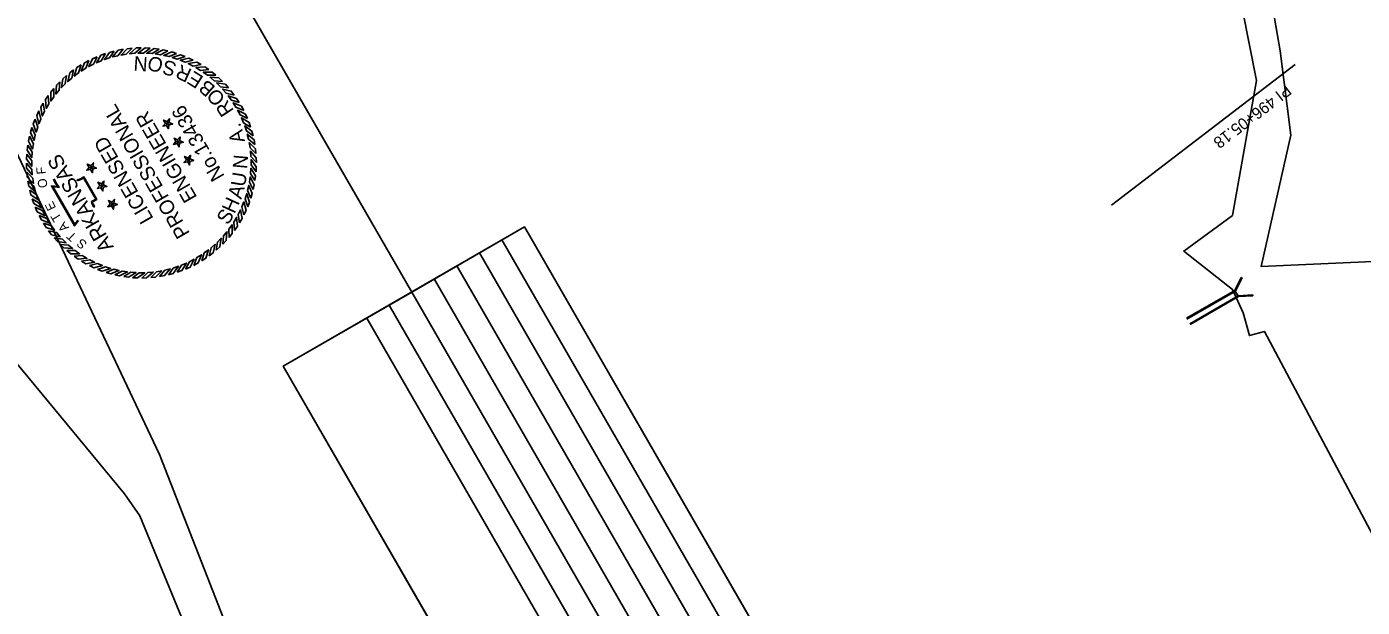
# Model space of a CAD drawing. Extents: x 956270 to 957915, y 1920520 to 1922423.
# Drawn here: x 956617 to 957310, y 1921739 to 1922039 of the extents above; entities that cross this region are included whole.
import ezdxf

# ---------------------------------------------------------------- set-up
doc = ezdxf.new("R2010")
doc.units = 0
for name, color, linetype in [('1', 7, 'Continuous'), ('Default', 7, 'Continuous'), ('G-ANNO-SYMB', 7, 'Continuous'), ('NO PLOT', 7, 'Continuous'), ('R_Drainage', 7, 'Continuous'), ('R_Horz Alg Annot', 7, 'Continuous')]:
    doc.layers.add(name, color=color, linetype=linetype)

msp = doc.modelspace()

# ---------------------------------------------------------------- linework, layer by layer
at = {"layer": '1'}
msp.add_line((956816.66, 1921901.98), (956666.17, 1922162.65), dxfattribs=at)
at = {"layer": 'Default'}
for p, q in [((956749.98, 1921863.48), (956875.12, 1921935.73)), ((957087.62, 1921567.67), (956875.12, 1921935.73)), ((957075.93, 1921560.92), (956863.43, 1921928.98)), ((957064.24, 1921554.17), (956851.74, 1921922.23)), ((957052.55, 1921547.42), (956840.05, 1921915.48)), ((957040.85, 1921540.67), (956828.35, 1921908.73)), ((957040.85, 1921540.67), (956828.35, 1921908.73)), ((957029.16, 1921533.92), (956816.66, 1921901.98)), ((957017.47, 1921527.17), (956804.97, 1921895.23)), ((957005.78, 1921520.42), (956793.28, 1921888.48)), ((956962.48, 1921495.42), (956749.98, 1921863.48))]:
    msp.add_line(p, q, dxfattribs=at)
at = {"layer": 'G-ANNO-SYMB'}
for points in [[(956657.79, 1922025.59), (956655.37, 1922024.73), (956653.02, 1922020.81), (956655.57, 1922021.89)], [(956662.3, 1922026.87), (956659.82, 1922026.21), (956657.17, 1922022.49), (956659.8, 1922023.36)], [(956666.89, 1922027.79), (956664.37, 1922027.33), (956661.43, 1922023.83), (956664.12, 1922024.49)], [(956671.54, 1922028.35), (956668.99, 1922028.09), (956665.79, 1922024.83), (956668.52, 1922025.28)], [(956676.22, 1922028.55), (956673.66, 1922028.49), (956670.21, 1922025.49), (956672.97, 1922025.72)], [(956680.9, 1922028.38), (956678.34, 1922028.52), (956674.67, 1922025.8), (956677.44, 1922025.81)], [(956685.56, 1922027.84), (956683.02, 1922028.18), (956679.14, 1922025.76), (956681.9, 1922025.55)], [(956690.15, 1922026.93), (956687.65, 1922027.47), (956683.59, 1922025.36), (956686.33, 1922024.94)], [(956694.67, 1922025.67), (956692.21, 1922026.41), (956688, 1922024.62), (956690.7, 1922023.99)], [(956645.07, 1922019.68), (956642.92, 1922018.29), (956641.54, 1922013.93), (956643.78, 1922015.57)], [(956649.15, 1922021.98), (956646.9, 1922020.76), (956645.18, 1922016.52), (956647.54, 1922017.98)], [(956653.4, 1922023.95), (956651.06, 1922022.92), (956649.02, 1922018.82), (956651.48, 1922020.1)], [(956699.07, 1922024.06), (956696.67, 1922024.99), (956692.34, 1922023.54), (956694.98, 1922022.7)], [(956703.32, 1922022.11), (956701.01, 1922023.22), (956696.57, 1922022.12), (956699.14, 1922021.07)], [(956707.42, 1922019.83), (956705.2, 1922021.12), (956700.69, 1922020.37), (956703.16, 1922019.12)], [(956711.32, 1922017.24), (956709.21, 1922018.7), (956704.65, 1922018.3), (956707.02, 1922016.86)], [(956637.51, 1922014.16), (956635.6, 1922012.45), (956634.93, 1922007.93), (956636.88, 1922009.9)], [(956641.18, 1922017.07), (956639.15, 1922015.51), (956638.12, 1922011.06), (956640.21, 1922012.87)], [(956715, 1922014.35), (956713.01, 1922015.97), (956708.44, 1922015.93), (956710.69, 1922014.31)], [(956718.45, 1922011.18), (956716.59, 1922012.95), (956712.03, 1922013.27), (956714.15, 1922011.48)], [(956630.91, 1922007.53), (956629.29, 1922005.54), (956629.33, 1922000.96), (956630.95, 1922003.22)], [(956634.08, 1922010.97), (956632.31, 1922009.12), (956631.99, 1922004.56), (956633.78, 1922006.67)], [(956721.64, 1922007.75), (956719.93, 1922009.66), (956715.4, 1922010.33), (956717.37, 1922008.38)], [(956724.55, 1922004.07), (956722.99, 1922006.11), (956718.54, 1922007.14), (956720.35, 1922005.04)], [(956625.42, 1921999.94), (956624.14, 1921997.72), (956624.89, 1921993.21), (956626.14, 1921995.69)], [(956628.02, 1922003.84), (956626.56, 1922001.73), (956626.96, 1921997.17), (956628.39, 1921999.55)], [(956727.16, 1922000.18), (956725.77, 1922002.34), (956721.41, 1922003.71), (956723.05, 1922001.48)], [(956729.46, 1921996.1), (956728.24, 1921998.36), (956724, 1922000.07), (956725.46, 1921997.72)], [(956621.19, 1921991.59), (956620.27, 1921989.2), (956621.72, 1921984.86), (956622.56, 1921987.5)], [(956623.15, 1921995.85), (956622.04, 1921993.53), (956623.14, 1921989.1), (956624.19, 1921991.66)], [(956689.9, 1921989.3), (956689.68, 1921990.32), (956687.87, 1921991.13), (956688.86, 1921989.41)], [(956689.9, 1921989.3), (956690.8, 1921989.82), (956691.01, 1921991.79), (956689.68, 1921990.32)], [(956731.43, 1921991.85), (956730.39, 1921994.2), (956726.3, 1921996.24), (956727.57, 1921993.78)], [(956733.06, 1921987.46), (956732.21, 1921989.88), (956728.29, 1921992.24), (956729.37, 1921989.68)], [(956619.58, 1921987.19), (956618.85, 1921984.73), (956620.64, 1921980.52), (956621.27, 1921983.22)], [(956689.9, 1921989.3), (956688.86, 1921989.41), (956687.54, 1921987.94), (956689.48, 1921988.35)], [(956689.9, 1921989.3), (956689.48, 1921988.35), (956690.47, 1921986.63), (956690.67, 1921988.6)], [(956689.9, 1921989.3), (956690.67, 1921988.6), (956692.61, 1921989.02), (956690.8, 1921989.82)], [(956734.34, 1921982.96), (956733.69, 1921985.44), (956729.96, 1921988.09), (956730.83, 1921985.46)], [(956735.27, 1921978.36), (956734.81, 1921980.89), (956731.3, 1921983.83), (956731.97, 1921981.14)], [(956617.42, 1921978.08), (956617.08, 1921975.54), (956619.5, 1921971.66), (956619.7, 1921974.43)], [(956618.32, 1921982.68), (956617.78, 1921980.17), (956619.89, 1921976.11), (956620.31, 1921978.85)], [(956695.36, 1921979.85), (956694.32, 1921979.96), (956692.99, 1921978.49), (956694.93, 1921978.9)], [(956695.36, 1921979.85), (956695.14, 1921980.87), (956693.33, 1921981.68), (956694.32, 1921979.96)], [(956695.36, 1921979.85), (956694.93, 1921978.9), (956695.92, 1921977.19), (956696.13, 1921979.16)], [(956695.36, 1921979.85), (956696.26, 1921980.37), (956696.46, 1921982.34), (956695.14, 1921980.87)], [(956695.36, 1921979.85), (956696.13, 1921979.16), (956698.07, 1921979.57), (956696.26, 1921980.37)], [(956735.83, 1921973.71), (956735.57, 1921976.27), (956732.31, 1921979.47), (956732.76, 1921976.74)], [(956616.88, 1921973.43), (956616.74, 1921970.87), (956619.46, 1921967.19), (956619.44, 1921969.96)], [(956700.81, 1921970.41), (956699.77, 1921970.51), (956698.45, 1921969.04), (956700.39, 1921969.45)], [(956700.81, 1921970.41), (956700.59, 1921971.42), (956698.78, 1921972.23), (956699.77, 1921970.51)], [(956700.81, 1921970.41), (956700.39, 1921969.45), (956701.38, 1921967.74), (956701.58, 1921969.71)], [(956700.81, 1921970.41), (956701.71, 1921970.93), (956701.92, 1921972.9), (956700.59, 1921971.42)], [(956700.81, 1921970.41), (956701.58, 1921969.71), (956703.52, 1921970.12), (956701.71, 1921970.93)], [(956736.03, 1921969.03), (956735.96, 1921971.6), (956732.96, 1921975.05), (956733.2, 1921972.29)], [(956735.85, 1921964.35), (956735.99, 1921966.91), (956733.27, 1921970.59), (956733.29, 1921967.82)], [(956616.71, 1921968.75), (956616.77, 1921966.18), (956619.77, 1921962.73), (956619.54, 1921965.49)], [(956616.9, 1921964.07), (956617.17, 1921961.51), (956620.43, 1921958.31), (956619.98, 1921961.04)], [(956650.34, 1921966.46), (956649.3, 1921966.57), (956647.98, 1921965.1), (956649.91, 1921965.51)], [(956650.34, 1921966.46), (956650.12, 1921967.48), (956648.31, 1921968.28), (956649.3, 1921966.57)], [(956650.34, 1921966.46), (956649.91, 1921965.51), (956650.91, 1921963.79), (956651.11, 1921965.76)], [(956650.34, 1921966.46), (956651.24, 1921966.98), (956651.45, 1921968.95), (956650.12, 1921967.48)], [(956650.34, 1921966.46), (956651.11, 1921965.76), (956653.05, 1921966.17), (956651.24, 1921966.98)], [(956735.31, 1921959.7), (956735.65, 1921962.24), (956733.23, 1921966.12), (956733.03, 1921963.36)], [(956617.46, 1921959.42), (956617.93, 1921956.89), (956621.43, 1921953.95), (956620.77, 1921956.64)], [(956655.79, 1921957.01), (956654.76, 1921957.12), (956653.43, 1921955.65), (956655.37, 1921956.06)], [(956655.79, 1921957.01), (956655.58, 1921958.03), (956653.77, 1921958.84), (956654.76, 1921957.12)], [(956655.79, 1921957.01), (956655.37, 1921956.06), (956656.36, 1921954.34), (956656.57, 1921956.32)], [(956655.79, 1921957.01), (956656.7, 1921957.53), (956656.9, 1921959.5), (956655.58, 1921958.03)], [(956655.79, 1921957.01), (956656.57, 1921956.32), (956658.51, 1921956.73), (956656.7, 1921957.53)], [(956733.15, 1921950.59), (956733.88, 1921953.05), (956732.1, 1921957.26), (956731.47, 1921954.56)], [(956734.41, 1921955.1), (956734.95, 1921957.61), (956732.84, 1921961.67), (956732.42, 1921958.93)], [(956618.39, 1921954.82), (956619.05, 1921952.34), (956622.77, 1921949.69), (956621.9, 1921952.32)], [(956619.67, 1921950.32), (956620.52, 1921947.9), (956624.44, 1921945.54), (956623.37, 1921948.1)], [(956661.25, 1921947.56), (956661.03, 1921948.58), (956659.22, 1921949.39), (956660.21, 1921947.67)], [(956661.25, 1921947.56), (956662.15, 1921948.09), (956662.36, 1921950.06), (956661.03, 1921948.58)], [(956731.54, 1921946.19), (956732.46, 1921948.59), (956731.01, 1921952.92), (956730.17, 1921950.28)], [(956621.3, 1921945.93), (956622.34, 1921943.58), (956626.43, 1921941.54), (956625.16, 1921944)], [(956661.25, 1921947.56), (956660.21, 1921947.67), (956658.89, 1921946.2), (956660.82, 1921946.61)], [(956661.25, 1921947.56), (956660.82, 1921946.61), (956661.81, 1921944.9), (956662.02, 1921946.87)], [(956661.25, 1921947.56), (956662.02, 1921946.87), (956663.96, 1921947.28), (956662.15, 1921948.09)], [(956727.31, 1921937.84), (956728.6, 1921940.06), (956727.84, 1921944.57), (956726.6, 1921942.09)], [(956729.59, 1921941.93), (956730.7, 1921944.25), (956729.59, 1921948.68), (956728.55, 1921946.12)], [(956623.28, 1921941.68), (956624.49, 1921939.42), (956628.73, 1921937.71), (956627.27, 1921940.06)], [(956625.57, 1921937.6), (956626.97, 1921935.44), (956631.33, 1921934.07), (956629.69, 1921936.3)], [(956721.83, 1921930.25), (956723.44, 1921932.24), (956723.4, 1921936.82), (956721.79, 1921934.57)], [(956724.72, 1921933.94), (956726.17, 1921936.05), (956725.78, 1921940.61), (956724.34, 1921938.23)], [(956628.19, 1921933.71), (956629.74, 1921931.67), (956634.2, 1921930.64), (956632.39, 1921932.74)], [(956631.09, 1921930.04), (956632.81, 1921928.13), (956637.33, 1921927.45), (956635.36, 1921929.4)], [(956715.22, 1921923.62), (956717.13, 1921925.33), (956717.81, 1921929.85), (956715.86, 1921927.88)], [(956718.65, 1921926.81), (956720.42, 1921928.66), (956720.74, 1921933.22), (956718.95, 1921931.11)], [(956634.28, 1921926.6), (956636.14, 1921924.83), (956640.7, 1921924.51), (956638.58, 1921926.3)], [(956637.73, 1921923.43), (956639.72, 1921921.81), (956644.29, 1921921.85), (956642.04, 1921923.47)], [(956707.66, 1921918.1), (956709.82, 1921919.49), (956711.19, 1921923.85), (956708.96, 1921922.21)], [(956711.55, 1921920.71), (956713.59, 1921922.27), (956714.62, 1921926.72), (956712.52, 1921924.91)], [(956641.42, 1921920.54), (956643.53, 1921919.08), (956648.08, 1921919.48), (956645.71, 1921920.92)], [(956645.32, 1921917.95), (956647.54, 1921916.66), (956652.05, 1921917.41), (956649.57, 1921918.66)], [(956649.41, 1921915.67), (956651.72, 1921914.56), (956656.16, 1921915.66), (956653.59, 1921916.71)], [(956653.67, 1921913.72), (956656.06, 1921912.79), (956660.4, 1921914.24), (956657.76, 1921915.09)], [(956690.43, 1921910.91), (956692.91, 1921911.57), (956695.57, 1921915.29), (956692.94, 1921914.42)], [(956694.94, 1921912.2), (956697.36, 1921913.05), (956699.71, 1921916.97), (956697.16, 1921915.89)], [(956699.33, 1921913.83), (956701.68, 1921914.87), (956703.72, 1921918.96), (956701.25, 1921917.69)], [(956703.58, 1921915.8), (956705.84, 1921917.02), (956707.55, 1921921.26), (956705.19, 1921919.8)], [(956658.07, 1921912.11), (956660.53, 1921911.37), (956664.74, 1921913.16), (956662.04, 1921913.79)], [(956662.58, 1921910.85), (956665.09, 1921910.31), (956669.14, 1921912.42), (956666.4, 1921912.84)], [(956667.18, 1921909.94), (956669.72, 1921909.6), (956673.6, 1921912.03), (956670.83, 1921912.23)], [(956671.83, 1921909.4), (956674.39, 1921909.26), (956678.07, 1921911.98), (956675.29, 1921911.97)], [(956676.51, 1921909.23), (956679.08, 1921909.29), (956682.53, 1921912.29), (956679.76, 1921912.06)], [(956681.19, 1921909.43), (956683.74, 1921909.69), (956686.95, 1921912.95), (956684.21, 1921912.5)], [(956685.84, 1921909.99), (956688.37, 1921910.45), (956691.3, 1921913.95), (956688.61, 1921913.29)]]:
    msp.add_lwpolyline(points, close=True, dxfattribs=at)
for points in [[(956643.65, 1921938.96), (956641.73, 1921936.25), (956629.69, 1921957.09), (956632.88, 1921956.61), (956632.05, 1921958.01), (956631.35, 1921959.19), (956630.8, 1921960.44)], [(956643.34, 1921939.18), (956641.77, 1921936.96), (956630.42, 1921956.59), (956633.62, 1921956.11), (956632.37, 1921958.21), (956631.69, 1921959.36), (956631.14, 1921960.6)], [(956642.8, 1921960), (956643.41, 1921959.77), (956644.06, 1921959.94), (956645.26, 1921960.47), (956646.38, 1921961.12), (956652.72, 1921950.14), (956651.1, 1921949.21), (956650.43, 1921948.82), (956650.63, 1921947.94), (956651.51, 1921946.41), (956651.33, 1921946.04)], [(956642.94, 1921960.36), (956643.43, 1921960.17), (956643.93, 1921960.3), (956645.08, 1921960.81), (956646.52, 1921961.64), (956653.24, 1921950), (956651.3, 1921948.88), (956650.86, 1921948.63), (956650.99, 1921948.08), (956651.95, 1921946.42), (956651.67, 1921945.87)]]:
    msp.add_lwpolyline(points, dxfattribs=at)
at = {"layer": 'NO PLOT'}
for points in [[(957915.18, 1921041.6), (957117.5, 1922423.23), (956666.17, 1922162.65), (956816.66, 1921901.98), (956875.12, 1921935.73), (957087.62, 1921567.67), (957029.16, 1921533.92), (957172.25, 1921286.08), (957225.74, 1921316.96), (957397.07, 1921020.21), (957343.58, 1920989.33), (957463.85, 1920781.02)], [(957915.18, 1921041.6), (957117.5, 1922423.23), (956666.17, 1922162.65), (956816.66, 1921901.98), (956875.12, 1921935.73), (957087.62, 1921567.67), (957029.16, 1921533.92), (957172.25, 1921286.08), (957225.74, 1921316.96), (957397.07, 1921020.21), (957343.58, 1920989.33), (957463.85, 1920781.02)], [(957915.18, 1921041.6), (957117.5, 1922423.23), (956666.17, 1922162.65), (956816.66, 1921901.98), (956875.12, 1921935.73), (957087.62, 1921567.67), (957029.16, 1921533.92), (957172.25, 1921286.08), (957225.74, 1921316.96), (957397.07, 1921020.21), (957343.58, 1920989.33), (957463.85, 1920781.02)], [(957915.18, 1921041.6), (957117.5, 1922423.23), (956666.17, 1922162.65), (956816.66, 1921901.98), (956875.12, 1921935.73), (957087.62, 1921567.67), (957029.16, 1921533.92), (957172.25, 1921286.08), (957225.74, 1921316.96), (957397.07, 1921020.21), (957343.58, 1920989.33), (957463.85, 1920781.02)], [(957012.51, 1920520.44), (956420.48, 1921545.87), (956463.26, 1921570.57), (956365.36, 1921740.14), (956378, 1921747.44), (956270.25, 1921934.07), (956666.17, 1922162.65), (956816.66, 1921901.98), (956749.98, 1921863.48), (956962.48, 1921495.42), (957029.16, 1921533.92), (957172.25, 1921286.08), (957120.9, 1921256.43), (957292.23, 1920959.68), (957343.58, 1920989.33), (957463.85, 1920781.02)], [(957012.51, 1920520.44), (956420.48, 1921545.87), (956463.26, 1921570.57), (956365.36, 1921740.14), (956378, 1921747.44), (956270.25, 1921934.07), (956666.17, 1922162.65), (956816.66, 1921901.98), (956749.98, 1921863.48), (956962.48, 1921495.42), (957029.16, 1921533.92), (957172.25, 1921286.08), (957120.9, 1921256.43), (957292.23, 1920959.68), (957343.58, 1920989.33), (957463.85, 1920781.02)], [(957012.51, 1920520.44), (956420.48, 1921545.87), (956463.26, 1921570.57), (956365.36, 1921740.14), (956378, 1921747.44), (956270.25, 1921934.07), (956666.17, 1922162.65), (956816.66, 1921901.98), (956749.98, 1921863.48), (956962.48, 1921495.42), (957029.16, 1921533.92), (957172.25, 1921286.08), (957120.9, 1921256.43), (957292.23, 1920959.68), (957343.58, 1920989.33), (957463.85, 1920781.02)], [(957012.51, 1920520.44), (956420.48, 1921545.87), (956463.26, 1921570.57), (956365.36, 1921740.14), (956378, 1921747.44), (956270.25, 1921934.07), (956666.17, 1922162.65), (956816.66, 1921901.98), (956749.98, 1921863.48), (956962.48, 1921495.42), (957029.16, 1921533.92), (957172.25, 1921286.08), (957120.9, 1921256.43), (957292.23, 1920959.68), (957343.58, 1920989.33), (957463.85, 1920781.02)]]:
    msp.add_lwpolyline(points, close=True, dxfattribs=at)
for points in [[(957342.58, 1921919.03), (957257.4, 1921915.24), (957272.85, 1921983.36), (957267.37, 1922027.06), (957246.99, 1922143.57)], [(957240.29, 1922085.93), (957255.08, 1922011.58), (957242.6, 1921941.72), (957217.28, 1921923.16), (957242.63, 1921903.32), (957248.1, 1921891.14), (957251.36, 1921879.39), (957259.14, 1921881.52), (957406.57, 1921604.71)], [(956978.43, 1921300.96), (956891.96, 1921416.34), (956761.21, 1921624.84), (956685.68, 1921817.75), (956598.64, 1922001.42), (956569.16, 1922006.84), (956549.42, 1922003.64), (956496.56, 1922078), (956484.6, 1922065.05), (956487.74, 1922034.93), (956520.15, 1921988.76), (956538.43, 1921986.13), (956552.84, 1921975.42), (956577.89, 1921905.71), (956667.63, 1921797.4), (956675.52, 1921785.98), (956734.33, 1921642.98), (956883.87, 1921386.21), (956963.43, 1921282.81)]]:
    msp.add_lwpolyline(points, dxfattribs=at)
at = {"layer": 'R_Drainage'}
for p, q in [((957247.09, 1921909.51), (957243.74, 1921902.8)), ((957247.54, 1921909.28), (957244.12, 1921902.44)), ((957247.09, 1921909.51), (957247.54, 1921909.28)), ((957218.72, 1921888.41), (957243.74, 1921902.8)), ((957218.96, 1921887.98), (957244.12, 1921902.44)), ((957242.87, 1921902.3), (957244.85, 1921899.1)), ((957243.74, 1921902.8), (957245.71, 1921899.6)), ((957220.4, 1921885.55), (957245.57, 1921900.08)), ((957220.65, 1921885.12), (957245.72, 1921899.59)), ((957253.18, 1921900.53), (957245.57, 1921900.08)), ((957253.2, 1921900.03), (957245.72, 1921899.59)), ((957253.2, 1921900.03), (957253.18, 1921900.53))]:
    msp.add_line(p, q, dxfattribs=at)
at = {"layer": 'R_Horz Alg Annot'}
msp.add_lwpolyline([(957179.79, 1921946.96), (957275.07, 1922019.91)], dxfattribs=at)

# ---------------------------------------------------------------- texts
at = {"layer": 'G-ANNO-SYMB'}
for s, height, rotation, p in [('N', 7.5, 176.10067, (956679.85, 1922023.72)), ('O', 7.5, 164.77573, (956688.31, 1922022.59)), ('S', 7.5, 163.48784, (956695.19, 1922020.61)), ('R', 7.5, 155.65967, (956703.05, 1922017.19)), ('E', 7.5, 147.83149, (956709.1, 1922013.36)), ('B', 7.5, 138.88501, (956715.23, 1922008.15)), ('O', 7.5, 131.42961, (956720.37, 1922002.44)), ('PROFESSIONAL', 7.5, 120, (956701.76, 1921932.41)), ('No.13436', 7.47, 120, (956719.78, 1921962.05)), ('R', 7.5, 123.22866, (956724.63, 1921996.03)), ('ENGINEER', 7.5, 120, (956705.48, 1921951.06)), ('A', 7.5, 103.09908, (956730.2, 1921980.12)), ('.', 7.5, 111.30002, (956728.4, 1921987.59)), ('LICENSED', 7.5, 120, (956682.86, 1921940.06)), ('ARKANSAS', 7.747, 120, (956662.16, 1921925.33)), ('N', 7.5, 84.93262, (956731.16, 1921965.58)), ('F', 4.75, 95.36282, (956626.82, 1921963.19)), ('U', 7.5, 80.90262, (956730.1, 1921956.24)), ('O', 4.75, 101.2218, (956627.85, 1921956.4)), ('A', 7.5, 73.44722, (956728.21, 1921949.75)), ('H', 7.5, 65.61905, (956724.66, 1921942.2)), ('E', 4.75, 116.67203, (956632.2, 1921945.6)), ('S', 7.5, 58.16364, (956721.28, 1921936.3)), ('T', 4.75, 121.47887, (956635.11, 1921940.27)), ('A', 4.75, 128.67877, (956639, 1921935.43)), ('T', 4.75, 136.90148, (956643.18, 1921931.19)), ('S', 4.75, 139.77256, (956648.55, 1921927.32))]:
    msp.add_text(s, height=height, rotation=rotation, dxfattribs=at).set_placement(p)
at = {"layer": 'R_Horz Alg Annot'}
msp.add_text('PI 496+05.18', height=6, rotation=217.43909, dxfattribs=at).set_placement((957270.17, 1922009.86))

doc.saveas('drawing.dxf')
